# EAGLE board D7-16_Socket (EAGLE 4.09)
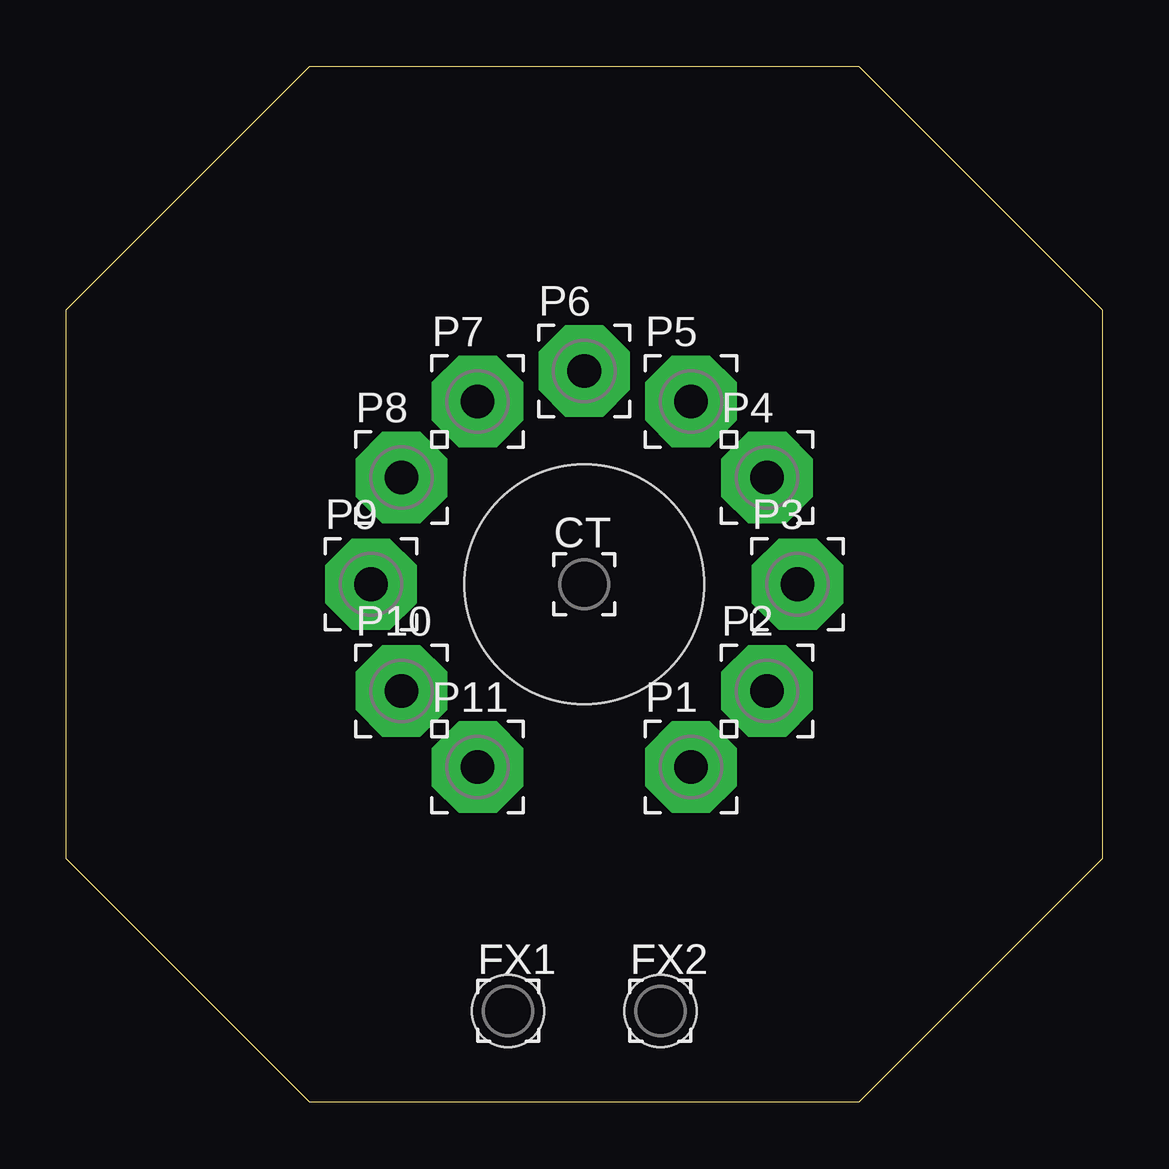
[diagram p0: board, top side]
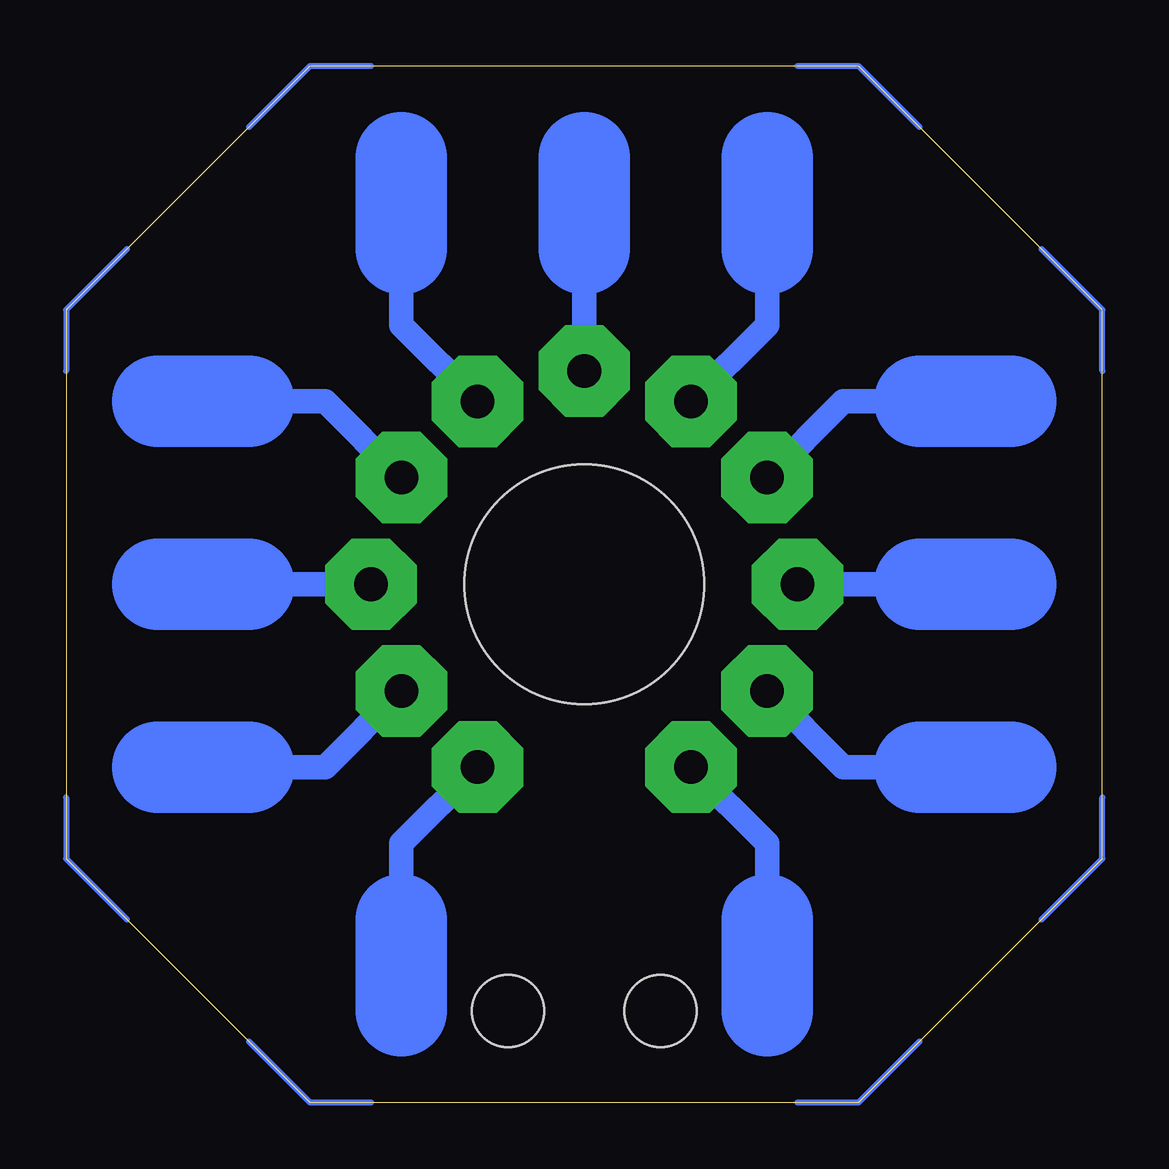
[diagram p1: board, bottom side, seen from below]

Size 43.18 x 43.18 mm. Coordinates in mm from the lower left corner, seen from the top.
Outline: 10.16,43.18 33.02,43.18 43.18,33.02 43.18,10.16 33.02,0 10.16,0 0,10.16 0,33.02 10.16,43.18
Copper layers used: Bottom
Holes 10 mm at 21.59,21.59
Holes 3 mm at 18.41,3.81 24.77,3.81

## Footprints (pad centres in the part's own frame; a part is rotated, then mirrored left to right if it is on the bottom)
2,54/1,0 = drill 1.016 pad 2.54 octagon: 1 0,0
2,54/1,1 = drill 1.118 pad 2.54 octagon: 1 0,0
3,81/1,4 = drill 1.397 pad 3.81 octagon: 1 0,0

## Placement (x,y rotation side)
CT  [2,54/1,0]  21.59,21.59 0 top
FX1  [2,54/1,1]  18.41,3.81 0 top
FX2  [2,54/1,1]  24.77,3.81 0 top
P1  [3,81/1,4]  26.04,13.97 0 top
P2  [3,81/1,4]  29.21,17.14 0 top
P3  [3,81/1,4]  30.48,21.59 0 top
P4  [3,81/1,4]  29.21,26.04 0 top
P5  [3,81/1,4]  26.04,29.21 0 top
P6  [3,81/1,4]  21.59,30.48 0 top
P7  [3,81/1,4]  17.14,29.21 0 top
P8  [3,81/1,4]  13.97,26.04 0 top
P9  [3,81/1,4]  12.7,21.59 0 top
P10  [3,81/1,4]  13.97,17.14 0 top
P11  [3,81/1,4]  17.14,13.97 0 top

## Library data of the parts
CT FX1 FX2 P1-P11 = wirepad

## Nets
S$1: P6.1
S$2: P5.1
S$3: P7.1
S$4: P9.1
S$5: P3.1
S$6: P1.1
S$7: P11.1
S$8: P10.1
S$9: P8.1
S$10: P4.1
S$11: P2.1

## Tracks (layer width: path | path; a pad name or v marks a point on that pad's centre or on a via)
S$1
  Bottom 1.016: P6.1 21.59,35.56
  Bottom 3.81: 21.59,35.56 21.59,39.37
S$2
  Bottom 1.016: P5.1 29.21,32.38 29.21,35.56
  Bottom 3.81: 29.21,35.56 29.21,39.37
S$3
  Bottom 1.016: P7.1 13.97,32.38 13.97,35.56
  Bottom 3.81: 13.97,35.56 13.97,39.37
S$4
  Bottom 1.016: 7.62,21.59 P9.1
  Bottom 3.81: 3.81,21.59 7.62,21.59
S$5
  Bottom 1.016: P3.1 35.56,21.59
  Bottom 3.81: 35.56,21.59 39.37,21.59
S$6
  Bottom 1.016: P1.1 29.21,10.79 29.21,7.62
  Bottom 3.81: 29.21,3.81 29.21,7.62
S$7
  Bottom 1.016: P11.1 13.97,10.79 13.97,7.62
  Bottom 3.81: 13.97,3.81 13.97,7.62
S$8
  Bottom 1.016: P10.1 10.79,13.97 7.62,13.97
  Bottom 3.81: 3.81,13.97 7.62,13.97
S$9
  Bottom 1.016: P8.1 10.79,29.21 7.62,29.21
  Bottom 3.81: 3.81,29.21 7.62,29.21
S$10
  Bottom 1.016: P4.1 32.38,29.21 35.56,29.21
  Bottom 3.81: 35.56,29.21 39.37,29.21
S$11
  Bottom 1.016: P2.1 32.38,13.97 35.56,13.97
  Bottom 3.81: 35.56,13.97 39.37,13.97
S$12
  Bottom 0.254: 7.62,40.64 10.16,43.18 12.7,43.18
S$13
  Bottom 0.254: 30.48,43.18 33.02,43.18 35.56,40.64
S$14
  Bottom 0.254: 40.64,35.56 43.18,33.02 43.18,30.48
S$15
  Bottom 0.254: 43.18,12.7 43.18,10.16 40.64,7.62
S$16
  Bottom 0.254: 35.56,2.54 33.02,0 30.48,0
S$17
  Bottom 0.254: 12.7,0 10.16,0 7.62,2.54
S$18
  Bottom 0.254: 2.54,7.62 0,10.16 0,12.7
S$19
  Bottom 0.254: 0,30.48 0,33.02 2.54,35.56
